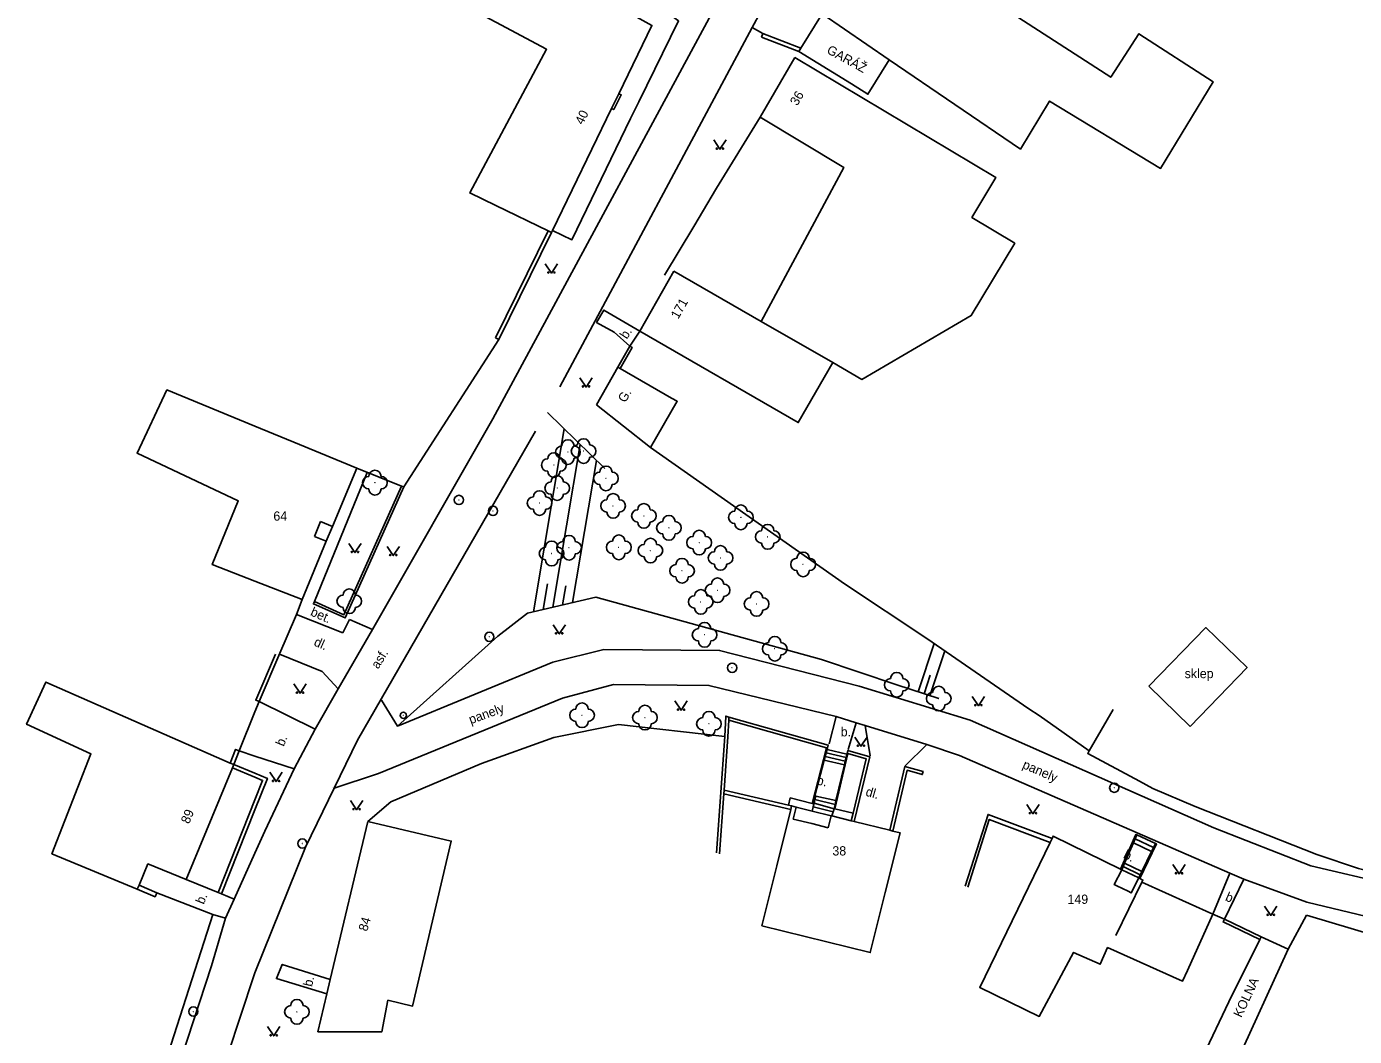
# Model space of a CAD drawing. Extents: x -582162 to -561283, y -1187583 to -1183539.
# Drawn here: x -570018.5 to -569910.9, y -1185455.6 to -1185373.8 of the extents above; entities that cross this region are included whole.
import ezdxf

# ---------------------------------------------------------------- set-up
doc = ezdxf.new("R2010")
doc.units = 0
for name, color, linetype in [('Vrstva 1', 7, 'Continuous'), ('Vrstva 10', 7, 'Continuous'), ('Vrstva 11', 7, 'Continuous'), ('Vrstva 12', 7, 'Continuous'), ('Vrstva 14', 7, 'Continuous'), ('Vrstva 3', 7, 'Continuous'), ('Vrstva 4', 7, 'Continuous'), ('Vrstva 5', 7, 'Continuous'), ('Vrstva 6', 7, 'Continuous'), ('Vrstva 9', 7, 'Continuous')]:
    doc.layers.add(name, color=color, linetype=linetype)

# ---------------------------------------------------------------- blocks, each defined once
blk = doc.blocks.new('1.079')
at = {"layer": 'Vrstva 1'}
for radius in [0.75, 0.001]:
    blk.add_circle((0, -0.001), radius, dxfattribs=at)
blk = doc.blocks.new('3.130')
at = {"layer": 'Vrstva 1'}
blk.add_circle((0, 0), 0.001, dxfattribs=at)
for centre, start, end in [((-1, 0), 90, 270), ((0, 1), 0, 180), ((1, 0), 270, 90), ((0, -1), 180, 360)]:
    blk.add_arc(centre, 1, start, end, dxfattribs=at)
blk = doc.blocks.new('3.140')
at = {"layer": 'Vrstva 1'}
blk.add_lwpolyline([(-1, 1.5), (0, 0), (1, 1.5)], dxfattribs=at)
for centre in [(-0.5, 0.1), (0.5, 0.1)]:
    blk.add_circle(centre, 0.1, dxfattribs=at)
blk = doc.blocks.new('4.110')
at = {"layer": 'Vrstva 1'}
for radius in [0.5, 0.001]:
    blk.add_circle((-0.001, 0), radius, dxfattribs=at)

msp = doc.modelspace()

# ---------------------------------------------------------------- linework, layer by layer
at = {"layer": 'Vrstva 10'}
for points in [[(-569975.32, -1185403), (-569959.73, -1185373.88), (-569957.7, -1185370.11), (-569944.87, -1185346.52), (-569933.12, -1185326.93), (-569932, -1185326.7), (-569931.54, -1185325.76)], [(-569940.63, -1185330.05), (-569941.62, -1185332.52), (-569942.07, -1185333.45), (-569944.16, -1185337.72), (-569960.3, -1185367.69), (-569980.73, -1185405.6)], [(-569958.86, -1185374.37), (-569959.73, -1185373.88)], [(-569958.97, -1185374.65), (-569955.94, -1185375.81)], [(-569971.11, -1185380.44), (-569970.94, -1185380.53), (-569970.33, -1185379.34), (-569970.53, -1185379.24)], [(-569976.25, -1185390.36), (-569980.51, -1185399.03)], [(-569969.63, -1185399.7), (-569970.9, -1185398.57), (-569972.33, -1185397.77), (-569971.74, -1185396.78), (-569968.84, -1185398.49)], [(-569991.69, -1185431.63), (-569977.27, -1185406.58)], [(-569980.73, -1185405.6), (-569990.48, -1185422.66)], [(-569995.18, -1185420.4), (-569990.91, -1185409.93)], [(-569996.63, -1185421.44), (-569992.87, -1185422.94)], [(-569990.48, -1185422.66), (-569993.25, -1185427.48)], [(-569992.87, -1185422.94), (-569992.35, -1185421.85)], [(-569992.35, -1185421.85), (-569990.48, -1185422.66)], [(-569998.02, -1185424.66), (-569994.56, -1185426.06)], [(-569942.06, -1185430.01), (-569951.06, -1185427.25), (-569962.37, -1185424.35), (-569971.73, -1185424.28), (-569975.87, -1185425.31), (-569988.46, -1185430.49), (-569989.76, -1185428.38)], [(-569994.56, -1185426.06), (-569993.25, -1185427.48)], [(-569995.12, -1185430.74), (-569993.25, -1185427.48)], [(-569993.66, -1185435.54), (-569990, -1185434.33), (-569975.1, -1185428.23), (-569970.97, -1185427.12), (-569963.23, -1185427.19), (-569952.93, -1185429.71), (-569953.5, -1185431.92)], [(-569995.12, -1185430.74), (-569999.66, -1185428.5)], [(-569952.93, -1185429.71), (-569951.3, -1185430.21)], [(-569951.95, -1185432.37), (-569951.3, -1185430.21)], [(-569951.3, -1185430.21), (-569950.57, -1185430.43), (-569950.16, -1185432.89)], [(-569914.48, -1185441.81), (-569922.34, -1185438.74), (-569942.06, -1185430.01)], [(-569996.83, -1185433.95), (-569995.12, -1185430.74)], [(-569950.57, -1185430.43), (-569945.59, -1185431.99)], [(-569995.91, -1185440.31), (-569991.69, -1185431.63)], [(-569953.66, -1185432.37), (-569952.05, -1185432.75)], [(-569947.35, -1185433.7), (-569945.59, -1185431.99)], [(-569945.59, -1185431.99), (-569942.94, -1185432.86)], [(-570001.29, -1185432.48), (-570000, -1185432.91)], [(-570000, -1185432.91), (-569996.83, -1185433.95)], [(-569953.89, -1185433.24), (-569952.26, -1185433.62)], [(-569953.81, -1185432.95), (-569952.19, -1185433.33)], [(-569953.73, -1185432.66), (-569952.12, -1185433.04)], [(-569942.94, -1185432.86), (-569921.05, -1185442.39), (-569919.91, -1185442.88), (-569914.8, -1185444.76)], [(-570000, -1185440.79), (-569999.19, -1185439), (-569996.83, -1185433.95)], [(-569956.79, -1185436.9), (-569956.65, -1185436.31), (-569954.87, -1185436.75)], [(-569954.64, -1185436.14), (-569954.57, -1185436.16)], [(-569954.57, -1185436.16), (-569952.94, -1185436.52)], [(-569954.87, -1185436.75), (-569954.8, -1185436.77)], [(-569953.02, -1185437.2), (-569953.09, -1185437.18)], [(-569951.56, -1185437.55), (-569953.02, -1185437.2)], [(-569927.38, -1185440.65), (-569928.84, -1185439.94)], [(-569928.7, -1185439.63), (-569927.22, -1185440.32)], [(-569928.56, -1185439.31), (-569927.07, -1185440)], [(-570001.68, -1185444.5), (-570000, -1185440.79)], [(-570000, -1185450.48), (-569995.91, -1185440.31)], [(-569928.3, -1185442.54), (-569929.69, -1185441.87)], [(-569928.17, -1185442.27), (-569929.57, -1185441.59)], [(-569819.84, -1185534.93), (-569824, -1185515.66), (-569825.76, -1185510.41), (-569829.79, -1185503.68), (-569840.47, -1185488.62), (-569851.43, -1185474.68), (-569857.44, -1185466.05), (-569860.38, -1185462.69), (-569863.09, -1185460.58), (-569878.75, -1185450.95), (-569882.22, -1185449.37), (-569914.48, -1185441.81)], [(-570002.98, -1185443.97), (-570005.56, -1185442.93)], [(-569922.43, -1185445.72), (-569921.05, -1185442.39)], [(-569919.91, -1185442.88), (-569921.47, -1185446.12)], [(-570002.7, -1185444.08), (-570001.68, -1185444.5), (-570002.38, -1185446.05), (-570003.4, -1185445.74)], [(-569914.8, -1185444.76), (-569905.25, -1185447.04), (-569902.94, -1185447.61), (-569882.9, -1185452.25), (-569880.17, -1185453.56), (-569864.74, -1185463.03), (-569862.27, -1185464.97), (-569859.74, -1185467.99), (-569853.84, -1185476.46), (-569842.51, -1185490.92), (-569832.14, -1185505.52), (-569828.61, -1185511.82), (-569826.91, -1185516.49), (-569823.08, -1185534.11)], [(-570002.38, -1185446.05), (-570003.53, -1185449.9), (-570015.25, -1185485.72)], [(-570002.19, -1185457.1), (-570000.1, -1185450.73), (-570000, -1185450.48)], [(-569993.9, -1185451.03), (-569997.79, -1185449.8), (-569998.26, -1185450.94), (-569994.18, -1185452.19)]]:
    msp.add_lwpolyline(points, dxfattribs=at)
at = {"layer": 'Vrstva 12'}
for points in [[(-569971.67, -1185409.62), (-569976.3, -1185405.07)], [(-569977.45, -1185421.22), (-569974.96, -1185406.39)], [(-569973.65, -1185407.68), (-569975.87, -1185420.85)], [(-569974.29, -1185420.48), (-569972.34, -1185408.96)], [(-569976.66, -1185421.03), (-569976.31, -1185418.95)], [(-569975.08, -1185420.66), (-569974.82, -1185419.11)], [(-569977.92, -1185421.33), (-569972.38, -1185420.03)], [(-569954.1, -1185425.09), (-569972.38, -1185420.03)], [(-569977.92, -1185421.33), (-569980.32, -1185423.21)], [(-569980.32, -1185423.21), (-569988.46, -1185430.49)], [(-569946.28, -1185427.71), (-569944.99, -1185423.79)], [(-569945.33, -1185428.03), (-569944.13, -1185424.38)], [(-569945.81, -1185427.87), (-569945.31, -1185426.36)]]:
    msp.add_lwpolyline(points, dxfattribs=at)
at = {"layer": 'Vrstva 4'}
for points in [[(-569991.83, -1185366.07), (-569989.4, -1185361.7), (-569967.85, -1185373.71), (-569970.53, -1185379.24)], [(-569955.78, -1185375.56), (-569954.06, -1185372.78)], [(-569959.07, -1185381.14), (-569956.28, -1185376.3)], [(-569955.94, -1185375.81), (-569955.78, -1185375.56)], [(-569951.69, -1185378.45), (-569955.94, -1185375.81)], [(-569970.53, -1185379.24), (-569971.11, -1185380.44)], [(-569971.11, -1185380.44), (-569975.9, -1185390.32)], [(-569976.25, -1185390.36), (-569980.48, -1185388.31)], [(-569975.98, -1185390.49), (-569976.25, -1185390.36)], [(-569975.9, -1185390.32), (-569975.98, -1185390.49)], [(-569968.84, -1185398.49), (-569966.07, -1185393.62)], [(-569972.35, -1185404.46), (-569970.6, -1185401.41)], [(-569970.6, -1185401.41), (-569970.43, -1185401.51)], [(-569970.43, -1185401.51), (-569966.26, -1185403.9)], [(-569972.35, -1185404.46), (-569967.95, -1185407.92)], [(-569991.76, -1185409.58), (-569996.38, -1185407.67)], [(-569993.73, -1185414.32), (-569991.76, -1185409.58)], [(-569994.7, -1185413.92), (-569993.73, -1185414.32)], [(-569995.19, -1185415.11), (-569994.22, -1185415.51)], [(-569994.22, -1185415.51), (-569993.73, -1185414.32)], [(-569996.18, -1185420.24), (-569994.22, -1185415.51)], [(-569927.61, -1185427.26), (-569924.26, -1185430.51)], [(-570002, -1185433.48), (-570001.72, -1185433.59)], [(-570001.83, -1185433.87), (-570005.56, -1185442.93)], [(-570001.72, -1185433.59), (-570001.83, -1185433.87)], [(-569954.78, -1185437.02), (-569954.71, -1185436.73)], [(-569954.71, -1185436.73), (-569954.64, -1185436.44)], [(-569953.09, -1185437.18), (-569954.71, -1185436.73)], [(-569954.64, -1185436.44), (-569954.57, -1185436.16)], [(-569953.01, -1185436.85), (-569954.64, -1185436.44)], [(-569956.6, -1185437.25), (-569957.73, -1185441.81)], [(-569956.53, -1185436.96), (-569956.6, -1185437.25)], [(-569956.16, -1185437.05), (-569956.53, -1185436.96)], [(-569954.89, -1185438.39), (-569956.4, -1185438.02), (-569956.16, -1185437.05)], [(-569954.87, -1185437.37), (-569956.16, -1185437.05)], [(-569954.87, -1185437.37), (-569954.78, -1185437.02)], [(-569953.34, -1185437.75), (-569954.87, -1185437.37)], [(-569953.18, -1185437.42), (-569954.78, -1185437.02)], [(-569953.57, -1185438.72), (-569953.34, -1185437.75)], [(-569953.27, -1185437.77), (-569953.34, -1185437.75)], [(-569953.27, -1185437.77), (-569953.18, -1185437.42)], [(-569951.71, -1185438.15), (-569953.27, -1185437.77)], [(-569953.18, -1185437.42), (-569953.09, -1185437.18)], [(-569990.86, -1185438.23), (-569993.9, -1185451.03)], [(-569951.47, -1185438.21), (-569951.71, -1185438.15)], [(-569948.57, -1185438.93), (-569951.47, -1185438.21)], [(-569948.95, -1185443.98), (-569947.75, -1185439.13), (-569948.33, -1185438.99)], [(-569948.33, -1185438.99), (-569948.57, -1185438.93)], [(-569935.6, -1185439.91), (-569935.44, -1185439.59)], [(-569935.44, -1185439.59), (-569935.35, -1185439.4), (-569929.89, -1185442.07)], [(-570005.56, -1185442.93), (-570008.67, -1185441.66), (-570009.39, -1185443.37)], [(-569929.89, -1185442.07), (-569929.8, -1185442.12)], [(-569930.2, -1185443.43), (-569930.4, -1185443.33), (-569929.8, -1185442.12)], [(-569928.17, -1185443.14), (-569930.28, -1185447.45)], [(-569929.8, -1185442.12), (-569928.42, -1185442.79)], [(-569929.28, -1185443.87), (-569929.02, -1185444), (-569928.42, -1185442.79)], [(-569928.42, -1185442.79), (-569928.33, -1185442.84)], [(-569928.33, -1185442.84), (-569928.08, -1185442.96), (-569928.17, -1185443.14)], [(-569928.17, -1185443.14), (-569922.43, -1185445.72)], [(-570009.39, -1185443.37), (-570009.53, -1185443.69)], [(-569922.43, -1185445.72), (-569924.48, -1185450.28)], [(-569918.6, -1185447.77), (-569918.5, -1185447.55)], [(-569918.5, -1185447.55), (-569916.32, -1185448.57)], [(-569993.9, -1185451.03), (-569994.18, -1185452.19)], [(-569994.18, -1185452.19), (-569994.91, -1185455.27)]]:
    msp.add_lwpolyline(points, dxfattribs=at)
at = {"layer": 'Vrstva 5'}
for points in [[(-569954.06, -1185372.78), (-569948.62, -1185376.49), (-569938, -1185383.73), (-569935.64, -1185379.84), (-569926.65, -1185385.29), (-569922.4, -1185378.28), (-569928.4, -1185374.39), (-569930.68, -1185377.91), (-569941.94, -1185370.61), (-569940.05, -1185367.69), (-569948.28, -1185362.35)], [(-569980.48, -1185388.31), (-569982.6, -1185387.28), (-569976.38, -1185375.64), (-569992.4, -1185367.08), (-569991.83, -1185366.07)], [(-569953.19, -1185401.02), (-569950.85, -1185402.39), (-569941.98, -1185397.22), (-569938.46, -1185391.36), (-569941.93, -1185389.27), (-569940, -1185386.02), (-569956.28, -1185376.3)], [(-569951.69, -1185378.45), (-569950.35, -1185379.28), (-569948.62, -1185376.49)], [(-569959.07, -1185381.14), (-569952.31, -1185385.22), (-569958.99, -1185397.7)], [(-569968.84, -1185398.49), (-569955.99, -1185405.89), (-569953.19, -1185401.02), (-569958.99, -1185397.7), (-569966.07, -1185393.62)], [(-570000, -1185406.18), (-570007.13, -1185403.25), (-570009.55, -1185408.36), (-570001.36, -1185412.24), (-570003.46, -1185417.4), (-570000, -1185418.75)], [(-569966.26, -1185403.9), (-569965.8, -1185404.16), (-569967.95, -1185407.92)], [(-569996.38, -1185407.67), (-570000, -1185406.18)], [(-570000, -1185418.75), (-569996.18, -1185420.24)], [(-569924.26, -1185430.51), (-569919.64, -1185425.75), (-569922.99, -1185422.5), (-569927.61, -1185427.26)], [(-570002, -1185433.48), (-570016.93, -1185426.92), (-570018.5, -1185430.33), (-570013.29, -1185432.73), (-570016.44, -1185440.83), (-570009.53, -1185443.69)], [(-569994.91, -1185455.27), (-569989.72, -1185455.26), (-569989.23, -1185452.7), (-569987.24, -1185453.17), (-569984.1, -1185439.8), (-569990.86, -1185438.23)], [(-569935.6, -1185439.91), (-569941.29, -1185451.68), (-569936.47, -1185454.01), (-569933.69, -1185448.83), (-569931.54, -1185449.79), (-569930.94, -1185448.44), (-569924.87, -1185451.15), (-569924.48, -1185450.28)], [(-569948.95, -1185443.98), (-569950.16, -1185448.84), (-569958.94, -1185446.66), (-569957.73, -1185441.81)], [(-569918.6, -1185447.77), (-569921.11, -1185452.82), (-569925.29, -1185461.57), (-569922.93, -1185462.73), (-569920.56, -1185457.85), (-569916.32, -1185448.57)]]:
    msp.add_lwpolyline(points, dxfattribs=at)
at = {"layer": 'Vrstva 9'}
for points in [[(-569974.54, -1185367.23), (-569967.46, -1185372.08), (-569965.69, -1185373.34), (-569968.91, -1185379.9)], [(-569958.97, -1185374.65), (-569958.86, -1185374.37), (-569955.78, -1185375.56)], [(-569969.58, -1185381.25), (-569968.91, -1185379.9)], [(-569969.58, -1185381.25), (-569974.33, -1185391.08), (-569975.9, -1185390.32)], [(-569962.61, -1185386.89), (-569959.07, -1185381.14)], [(-569962.61, -1185386.89), (-569964.45, -1185390.01)], [(-569966.82, -1185393.95), (-569964.45, -1185390.01)], [(-569975.98, -1185390.49), (-569980.24, -1185399.16)], [(-569980.24, -1185399.16), (-569980.51, -1185399.03)], [(-569968.84, -1185398.49), (-569969.63, -1185399.7)], [(-569980.24, -1185399.16), (-569987.94, -1185411.11)], [(-569969.63, -1185399.7), (-569970.6, -1185401.41)], [(-569969.63, -1185399.7), (-569969.46, -1185399.8), (-569970.43, -1185401.51)], [(-569967.95, -1185407.92), (-569952.26, -1185418.97)], [(-569988.12, -1185411.04), (-569991.76, -1185409.58)], [(-569987.94, -1185411.11), (-569992.69, -1185421.72), (-569995.26, -1185420.58), (-569995.18, -1185420.4), (-569992.79, -1185421.46), (-569988.12, -1185411.04)], [(-569987.94, -1185411.11), (-569988.12, -1185411.04)], [(-569995.19, -1185415.11), (-569994.7, -1185413.92)], [(-569945.57, -1185423.39), (-569952.26, -1185418.97)], [(-569998.07, -1185424.77), (-569996.63, -1185421.44), (-569996.18, -1185420.24)], [(-569937.33, -1185429.1), (-569945.57, -1185423.39)], [(-569999.66, -1185428.5), (-569999.94, -1185428.38), (-569998.35, -1185424.65)], [(-569998.07, -1185424.77), (-569999.66, -1185428.5)], [(-569954.1, -1185425.09), (-569948.02, -1185427.14), (-569944.62, -1185428.26)], [(-570000, -1185429.33), (-569999.66, -1185428.5)], [(-569937.33, -1185429.1), (-569936.48, -1185429.63)], [(-569932.43, -1185432.5), (-569930.49, -1185429.14)], [(-570001.29, -1185432.48), (-570000, -1185429.33)], [(-569962.01, -1185435.67), (-569961.7, -1185431.36), (-569961.63, -1185430.01)], [(-569961.95, -1185431.34), (-569961.87, -1185429.68), (-569961.62, -1185429.75)], [(-569961.63, -1185430.01), (-569961.62, -1185429.75)], [(-569961.63, -1185430.01), (-569953.7, -1185432.24)], [(-569961.62, -1185429.75), (-569953.56, -1185432.02), (-569953.63, -1185432.26)], [(-569932.43, -1185432.5), (-569936.48, -1185429.63)], [(-569975.79, -1185431.4), (-569970.56, -1185430.37), (-569961.95, -1185431.34)], [(-569962.62, -1185440.75), (-569961.95, -1185431.34)], [(-570001.29, -1185432.48), (-570001.57, -1185432.37), (-570002, -1185433.48)], [(-569975.79, -1185431.4), (-569981.66, -1185433.52)], [(-569954.87, -1185436.75), (-569953.7, -1185432.24)], [(-569953.73, -1185432.66), (-569953.66, -1185432.37)], [(-569953.7, -1185432.24), (-569953.63, -1185432.26)], [(-569953.66, -1185432.37), (-569953.63, -1185432.26)], [(-570001.29, -1185432.48), (-570001.72, -1185433.59)], [(-569954.64, -1185436.14), (-569953.89, -1185433.24)], [(-569953.89, -1185433.24), (-569953.81, -1185432.95)], [(-569953.81, -1185432.95), (-569953.73, -1185432.66)], [(-569951.97, -1185432.72), (-569953.02, -1185437.2)], [(-569952.19, -1185433.33), (-569952.26, -1185433.62)], [(-569952.12, -1185433.04), (-569952.19, -1185433.33)], [(-569952.05, -1185432.75), (-569952.12, -1185433.04)], [(-569952.04, -1185432.7), (-569952.05, -1185432.75)], [(-569951.47, -1185438.21), (-569950.19, -1185432.98), (-569951.97, -1185432.46), (-569952.04, -1185432.7)], [(-569951.97, -1185432.72), (-569952.04, -1185432.7)], [(-569951.56, -1185437.55), (-569950.49, -1185433.15), (-569951.97, -1185432.72)], [(-569928.36, -1185434.96), (-569932.55, -1185432.72), (-569932.43, -1185432.5)], [(-570000, -1185434.63), (-570001.83, -1185433.87)], [(-570001.72, -1185433.59), (-570000, -1185434.31)], [(-570000, -1185434.31), (-569998.99, -1185434.73), (-570000, -1185437.27)], [(-569990.86, -1185438.23), (-569989, -1185436.62), (-569981.66, -1185433.52)], [(-569952.26, -1185433.62), (-569952.94, -1185436.52)], [(-569948.57, -1185438.93), (-569947.36, -1185433.75), (-569945.88, -1185434.17), (-569945.95, -1185434.41), (-569947.18, -1185434.06), (-569948.33, -1185438.99)], [(-570000, -1185436.45), (-569999.38, -1185434.89), (-570000, -1185434.63)], [(-569928.36, -1185434.96), (-569927.27, -1185435.55)], [(-569883.16, -1185437.24), (-569893.26, -1185446.51), (-569910.63, -1185442.03), (-569913.98, -1185440.9), (-569923.86, -1185437), (-569927.27, -1185435.55)], [(-570002.98, -1185443.97), (-570000, -1185436.45)], [(-569962.38, -1185440.84), (-569962.03, -1185435.97)], [(-569962.03, -1185435.97), (-569962.01, -1185435.67)], [(-569962.03, -1185435.97), (-569956.6, -1185437.25)], [(-569956.79, -1185436.9), (-569962.01, -1185435.67)], [(-569954.8, -1185436.77), (-569954.64, -1185436.14)], [(-569952.94, -1185436.52), (-569953.01, -1185436.85)], [(-570000, -1185437.27), (-570002.7, -1185444.08)], [(-569956.53, -1185436.96), (-569956.79, -1185436.9)], [(-569953.01, -1185436.85), (-569953.09, -1185437.18)], [(-569951.71, -1185438.15), (-569951.56, -1185437.55)], [(-569935.44, -1185439.59), (-569940.62, -1185437.64), (-569942.47, -1185443.47)], [(-569953.57, -1185438.72), (-569954.89, -1185438.39)], [(-569942.26, -1185443.54), (-569940.52, -1185438.05), (-569935.6, -1185439.91)], [(-569928.56, -1185439.31), (-569928.65, -1185439.27), (-569929.89, -1185442.07)], [(-569929.57, -1185441.59), (-569928.84, -1185439.94)], [(-569928.84, -1185439.94), (-569928.7, -1185439.63)], [(-569928.7, -1185439.63), (-569928.56, -1185439.31)], [(-569927.07, -1185440), (-569926.98, -1185440.04), (-569928.33, -1185442.84)], [(-569928.17, -1185442.27), (-569927.38, -1185440.65)], [(-569927.38, -1185440.65), (-569927.22, -1185440.32)], [(-569927.22, -1185440.32), (-569927.07, -1185440)], [(-569929.8, -1185442.12), (-569929.69, -1185441.87)], [(-569929.69, -1185441.87), (-569929.57, -1185441.59)], [(-569928.42, -1185442.79), (-569928.3, -1185442.54)], [(-569928.3, -1185442.54), (-569928.17, -1185442.27)], [(-570009.53, -1185443.69), (-570008.09, -1185444.31), (-570007.95, -1185443.99)], [(-570009.39, -1185443.37), (-570007.95, -1185443.99)], [(-570007.95, -1185443.99), (-570003.4, -1185445.74)], [(-570002.7, -1185444.08), (-570002.98, -1185443.97)], [(-569929.28, -1185443.87), (-569930.2, -1185443.43)], [(-570003.4, -1185445.74), (-570009.45, -1185464.58), (-570015.22, -1185482.52)], [(-569921.47, -1185446.12), (-569922.43, -1185445.72)], [(-569921.47, -1185446.12), (-569921.58, -1185446.35), (-569918.6, -1185447.77)], [(-569921.47, -1185446.12), (-569918.5, -1185447.55)], [(-569916.32, -1185448.57), (-569914.84, -1185445.81)], [(-569914.84, -1185445.81), (-569903.45, -1185449.21)]]:
    msp.add_lwpolyline(points, dxfattribs=at)

# ---------------------------------------------------------------- block references
at = {"layer": 'Vrstva 1', "xscale": 0.5, "yscale": 0.5}
for p in [(-569983.48, -1185412.16), (-569981.02, -1185423.25), (-569961.35, -1185425.76), (-569930.4, -1185435.48), (-570004.99, -1185453.62)]:
    msp.add_blockref('1.079', p, dxfattribs=at)
at = {"layer": 'Vrstva 1', "xscale": 0.5, "yscale": 0.5, "rotation": 90}
for p in [(-569980.72, -1185413.05), (-569996.16, -1185440)]:
    msp.add_blockref('1.079', p, dxfattribs=at)
at = {"layer": 'Vrstva 11', "xscale": 0.5, "yscale": 0.5}
for p in [(-569974.65, -1185408.28), (-569973.38, -1185408.2), (-569975.79, -1185409.33), (-569990.28, -1185410.76), (-569971.57, -1185410.41), (-569975.52, -1185411.2), (-569976.95, -1185412.41), (-569970.99, -1185412.64), (-569968.5, -1185413.45), (-569960.64, -1185413.57), (-569966.47, -1185414.42), (-569974.56, -1185416.03), (-569970.53, -1185416), (-569964.02, -1185415.62), (-569958.47, -1185415.15), (-569975.97, -1185416.5), (-569967.97, -1185416.26), (-569962.29, -1185416.86), (-569965.41, -1185417.9), (-569955.6, -1185417.38), (-569992.36, -1185420.37), (-569963.89, -1185420.42), (-569962.53, -1185419.48), (-569959.37, -1185420.59), (-569963.58, -1185423.09), (-569957.9, -1185424.22), (-569948.02, -1185427.14), (-569944.62, -1185428.26), (-569973.51, -1185429.61), (-569968.41, -1185429.8), (-569963.23, -1185430.3), (-569996.6, -1185453.64)]:
    msp.add_blockref('3.130', p, dxfattribs=at)
at = {"layer": 'Vrstva 3', "xscale": 0.5, "yscale": 0.5}
for p in [(-569962.34, -1185383.74), (-569975.99, -1185393.78), (-569973.18, -1185403.01), (-569991.9, -1185416.43), (-569988.8, -1185416.67), (-569975.36, -1185423.02), (-569996.35, -1185427.82), (-569941.4, -1185428.84), (-569965.49, -1185429.2), (-569950.92, -1185432.12), (-569998.29, -1185434.98), (-569991.77, -1185437.27), (-569936.99, -1185437.59), (-569925.15, -1185442.46), (-569917.72, -1185445.83), (-569998.48, -1185455.59)]:
    msp.add_blockref('3.140', p, dxfattribs=at)
at = {"layer": 'Vrstva 9', "xscale": 0.5, "yscale": 0.5}
msp.add_blockref('4.110', (-569987.98, -1185429.62), dxfattribs=at)

# ---------------------------------------------------------------- texts
at = {"layer": 'Vrstva 14'}
for s, rotation, p in [('GARÁŽ', 331.269, (-569953.75, -1185375.92)), ('b.', 56.86, (-569969.88, -1185399.18)), ('G.', 60.195, (-569970, -1185404.33)), ('bet.', 336.236, (-569995.57, -1185421.49)), ('dl.', 336.236, (-569995.29, -1185423.93)), ('asf.', 58.106, (-569990.02, -1185425.91)), ('panely', 20.058, (-569982.52, -1185430.34)), ('b.', 67.729, (-569997.67, -1185432.18)), ('panely', 336.467, (-569937.9, -1185433.87)), (' b.', 346.823, (-569954.83, -1185435.14)), (' dl.', 344.157, (-569950.86, -1185436.04)), (' b.', 333.702, (-569929.97, -1185441.02)), ('b.', 67.729, (-570004.15, -1185444.98)), ('b.', 336.467, (-569921.47, -1185444.59)), ('b.', 76.63, (-569995.38, -1185451.65)), ('KOLNA', 64.754, (-569920.11, -1185454.16))]:
    msp.add_text(s, height=0.75, rotation=rotation, dxfattribs=at).set_placement(p)
for s, p in [('sklep', (-569924.7, -1185426.6)), ('b.', (-569952.56, -1185431.32))]:
    msp.add_text(s, height=0.75, dxfattribs=at).set_placement(p)
at = {"layer": 'Vrstva 6'}
for s, rotation, p in [('36', 58.884, (-569956.08, -1185380.27)), ('40', 64.15, (-569973.44, -1185381.81)), ('171', 60.369, (-569965.72, -1185397.55)), ('89', 67.651, (-570005.34, -1185438.46)), ('84', 73.38, (-569990.92, -1185447.17))]:
    msp.add_text(s, height=0.75, rotation=rotation, dxfattribs=at).set_placement(p)
for s, p in [('64', (-569998.51, -1185413.84)), ('38', (-569953.23, -1185440.97)), ('149', (-569934.19, -1185444.89))]:
    msp.add_text(s, height=0.75, dxfattribs=at).set_placement(p)

doc.saveas('drawing.dxf')
